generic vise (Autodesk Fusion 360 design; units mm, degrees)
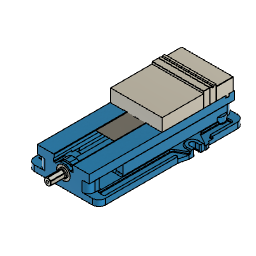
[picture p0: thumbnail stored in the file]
parameter "stockY" = 152.4
base_feature "Base Feature1" bodies "Bushing", "Cover", "Casting"
base_feature "Base Feature1" bodies "Nut"
base_feature "Base Feature1"
base_feature "Base Feature1"
as_built_joint "As-built1"
as_built_joint "As-built2"
as_built_joint "As-built3" OffsetX 0 OffsetY 0 OffsetZ 0 AngleZ 0 DistanceMaximum 0 DistanceMinimum -215.9
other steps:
create_component "CreateComponent1"
create_component "CreateComponent1"
create_component "CreateComponent2"
create_component "CreateComponent3"
named bodies: "Bushing", "Cover", "Casting", "Nut"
